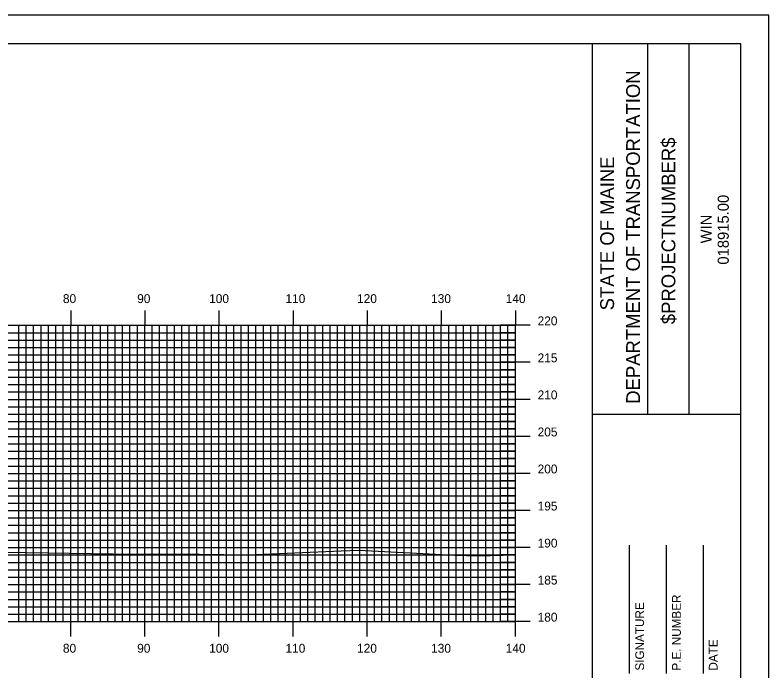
# Model space of a CAD drawing. Extents: x 1812948 to 1813291, y 442591 to 442811.
# Drawn here: x 1813186 to 1813287.7, y 442722 to 442810.5 of the extents above; entities that cross this region are included whole.
import ezdxf

# ---------------------------------------------------------------- set-up
doc = ezdxf.new("R2010")
doc.units = 0
for name, color, linetype in [('BORDER', 7, 'Continuous'), ('H_V ANNOTATION', 7, 'Continuous'), ('MAJOR', 7, 'Continuous'), ('MINOR', 7, 'Continuous'), ('PLOT BOUNDARY', 7, 'Continuous'), ('S_Roadway_Centerline', 7, 'Continuous')]:
    doc.layers.add(name, color=color, linetype=linetype)

msp = doc.modelspace()

# ---------------------------------------------------------------- linework, layer by layer
at = {"layer": 'BORDER'}
for p, q in [((1813263.86, 442596.67), (1813263.86, 442806.67)), ((1813271.31, 442756.66), (1813271.31, 442806.66)), ((1813276.9, 442756.66), (1813276.9, 442806.66)), ((1813263.86, 442756.65), (1813283.86, 442756.65)), ((1813268.86, 442721.67), (1813268.86, 442738.97)), ((1813273.86, 442721.67), (1813273.86, 442738.97)), ((1813278.86, 442721.67), (1813278.86, 442738.97))]:
    msp.add_line(p, q, dxfattribs=at)
msp.add_lwpolyline([(1812963.86, 442596.67), (1813283.86, 442596.67), (1813283.86, 442806.67), (1812963.86, 442806.67)], close=True, dxfattribs=at)
at = {"layer": 'MAJOR'}
for p, q in [((1813193.46, 442770.67), (1813193.46, 442768.67)), ((1813203.46, 442770.67), (1813203.46, 442768.67)), ((1813213.46, 442770.67), (1813213.46, 442768.67)), ((1813223.46, 442770.67), (1813223.46, 442768.67)), ((1813233.46, 442770.67), (1813233.46, 442768.67)), ((1813243.46, 442770.67), (1813243.46, 442768.67)), ((1813253.46, 442770.67), (1813253.46, 442768.67)), ((1812973.46, 442768.67), (1813253.46, 442768.67)), ((1812973.46, 442768.67), (1813253.46, 442768.67)), ((1813193.46, 442728.67), (1813193.46, 442768.67)), ((1813203.46, 442728.67), (1813203.46, 442768.67)), ((1813213.46, 442728.67), (1813213.46, 442768.67)), ((1813223.46, 442728.67), (1813223.46, 442768.67)), ((1813233.46, 442728.67), (1813233.46, 442768.67)), ((1813243.46, 442728.67), (1813243.46, 442768.67)), ((1813255.46, 442768.67), (1813251.45, 442768.67)), ((1813253.46, 442728.67), (1813253.46, 442768.67)), ((1813253.46, 442728.67), (1813253.46, 442768.67)), ((1812973.46, 442763.67), (1813253.46, 442763.67)), ((1813255.46, 442763.67), (1813251.45, 442763.67)), ((1812973.46, 442758.67), (1813253.46, 442758.67)), ((1813255.46, 442758.67), (1813251.45, 442758.67)), ((1812973.46, 442753.67), (1813253.46, 442753.67)), ((1813255.46, 442753.67), (1813251.45, 442753.67)), ((1812973.46, 442748.67), (1813253.46, 442748.67)), ((1813255.46, 442748.67), (1813251.45, 442748.67)), ((1812973.46, 442743.67), (1813253.46, 442743.67)), ((1813255.46, 442743.67), (1813251.45, 442743.67)), ((1812973.46, 442738.67), (1813253.46, 442738.67)), ((1813255.46, 442738.67), (1813251.45, 442738.67)), ((1812973.46, 442733.67), (1813253.46, 442733.67)), ((1813255.46, 442733.67), (1813251.45, 442733.67)), ((1812973.46, 442728.67), (1813253.46, 442728.67)), ((1812973.46, 442728.67), (1813253.46, 442728.67)), ((1813193.46, 442726.66), (1813193.46, 442728.67)), ((1813203.46, 442726.66), (1813203.46, 442728.67)), ((1813213.46, 442726.66), (1813213.46, 442728.67)), ((1813223.46, 442726.66), (1813223.46, 442728.67)), ((1813233.46, 442726.66), (1813233.46, 442728.67)), ((1813243.46, 442726.66), (1813243.46, 442728.67)), ((1813255.46, 442728.67), (1813251.45, 442728.67)), ((1813253.46, 442726.66), (1813253.46, 442728.67))]:
    msp.add_line(p, q, dxfattribs=at)
at = {"layer": 'MINOR'}
for p, q in [((1813186.46, 442728.67), (1813186.46, 442768.67)), ((1813187.46, 442728.67), (1813187.46, 442768.67)), ((1813188.46, 442728.67), (1813188.46, 442768.67)), ((1813189.46, 442728.67), (1813189.46, 442768.67)), ((1813190.46, 442728.67), (1813190.46, 442768.67)), ((1813191.46, 442728.67), (1813191.46, 442768.67)), ((1813192.46, 442728.67), (1813192.46, 442768.67)), ((1813194.46, 442728.67), (1813194.46, 442768.67)), ((1813195.46, 442728.67), (1813195.46, 442768.67)), ((1813196.46, 442728.67), (1813196.46, 442768.67)), ((1813197.46, 442728.67), (1813197.46, 442768.67)), ((1813198.46, 442728.67), (1813198.46, 442768.67)), ((1813199.46, 442728.67), (1813199.46, 442768.67)), ((1813200.46, 442728.67), (1813200.46, 442768.67)), ((1813201.46, 442728.67), (1813201.46, 442768.67)), ((1813202.46, 442728.67), (1813202.46, 442768.67)), ((1813204.46, 442728.67), (1813204.46, 442768.67)), ((1813205.46, 442728.67), (1813205.46, 442768.67)), ((1813206.46, 442728.67), (1813206.46, 442768.67)), ((1813207.46, 442728.67), (1813207.46, 442768.67)), ((1813208.46, 442728.67), (1813208.46, 442768.67)), ((1813209.46, 442728.67), (1813209.46, 442768.67)), ((1813210.46, 442728.67), (1813210.46, 442768.67)), ((1813211.46, 442728.67), (1813211.46, 442768.67)), ((1813212.46, 442728.67), (1813212.46, 442768.67)), ((1813214.46, 442728.67), (1813214.46, 442768.67)), ((1813215.46, 442728.67), (1813215.46, 442768.67)), ((1813216.46, 442728.67), (1813216.46, 442768.67)), ((1813217.46, 442728.67), (1813217.46, 442768.67)), ((1813218.46, 442728.67), (1813218.46, 442768.67)), ((1813219.46, 442728.67), (1813219.46, 442768.67)), ((1813220.46, 442728.67), (1813220.46, 442768.67)), ((1813221.46, 442728.67), (1813221.46, 442768.67)), ((1813222.46, 442728.67), (1813222.46, 442768.67)), ((1813224.46, 442728.67), (1813224.46, 442768.67)), ((1813225.46, 442728.67), (1813225.46, 442768.67)), ((1813226.46, 442728.67), (1813226.46, 442768.67)), ((1813227.46, 442728.67), (1813227.46, 442768.67)), ((1813228.46, 442728.67), (1813228.46, 442768.67)), ((1813229.46, 442728.67), (1813229.46, 442768.67)), ((1813230.46, 442728.67), (1813230.46, 442768.67)), ((1813231.46, 442728.67), (1813231.46, 442768.67)), ((1813232.46, 442728.67), (1813232.46, 442768.67)), ((1813234.46, 442728.67), (1813234.46, 442768.67)), ((1813235.46, 442728.67), (1813235.46, 442768.67)), ((1813236.46, 442728.67), (1813236.46, 442768.67)), ((1813237.46, 442728.67), (1813237.46, 442768.67)), ((1813238.46, 442728.67), (1813238.46, 442768.67)), ((1813239.46, 442728.67), (1813239.46, 442768.67)), ((1813240.46, 442728.67), (1813240.46, 442768.67)), ((1813241.46, 442728.67), (1813241.46, 442768.67)), ((1813242.46, 442728.67), (1813242.46, 442768.67)), ((1813244.46, 442728.67), (1813244.46, 442768.67)), ((1813245.46, 442728.67), (1813245.46, 442768.67)), ((1813246.46, 442728.67), (1813246.46, 442768.67)), ((1813247.46, 442728.67), (1813247.46, 442768.67)), ((1813248.46, 442728.67), (1813248.46, 442768.67)), ((1813249.46, 442728.67), (1813249.46, 442768.67)), ((1813250.46, 442728.67), (1813250.46, 442768.67)), ((1813251.46, 442728.67), (1813251.46, 442768.67)), ((1813252.46, 442728.67), (1813252.46, 442768.67)), ((1812973.46, 442767.67), (1813253.46, 442767.67)), ((1813253.46, 442767.67), (1813251.45, 442767.67)), ((1812973.46, 442766.67), (1813253.46, 442766.67)), ((1813253.46, 442766.67), (1813251.45, 442766.67)), ((1812973.46, 442765.67), (1813253.46, 442765.67)), ((1813253.46, 442765.67), (1813251.45, 442765.67)), ((1812973.46, 442764.67), (1813253.46, 442764.67)), ((1813253.46, 442764.67), (1813251.45, 442764.67)), ((1812973.46, 442762.67), (1813253.46, 442762.67)), ((1813253.46, 442762.67), (1813251.45, 442762.67)), ((1812973.46, 442761.67), (1813253.46, 442761.67)), ((1813253.46, 442761.67), (1813251.45, 442761.67)), ((1812973.46, 442760.67), (1813253.46, 442760.67)), ((1813253.46, 442760.67), (1813251.45, 442760.67)), ((1812973.46, 442759.67), (1813253.46, 442759.67)), ((1813253.46, 442759.67), (1813251.45, 442759.67)), ((1812973.46, 442757.67), (1813253.46, 442757.67)), ((1813253.46, 442757.67), (1813251.45, 442757.67)), ((1812973.46, 442756.67), (1813253.46, 442756.67)), ((1813253.46, 442756.67), (1813251.45, 442756.67)), ((1812973.46, 442755.67), (1813253.46, 442755.67)), ((1813253.46, 442755.67), (1813251.45, 442755.67)), ((1812973.46, 442754.67), (1813253.46, 442754.67)), ((1813253.46, 442754.67), (1813251.45, 442754.67)), ((1812973.46, 442752.67), (1813253.46, 442752.67)), ((1813253.46, 442752.67), (1813251.45, 442752.67)), ((1812973.46, 442751.67), (1813253.46, 442751.67)), ((1813253.46, 442751.67), (1813251.45, 442751.67)), ((1812973.46, 442750.67), (1813253.46, 442750.67)), ((1813253.46, 442750.67), (1813251.45, 442750.67)), ((1812973.46, 442749.67), (1813253.46, 442749.67)), ((1813253.46, 442749.67), (1813251.45, 442749.67)), ((1812973.46, 442747.67), (1813253.46, 442747.67)), ((1813253.46, 442747.67), (1813251.45, 442747.67)), ((1812973.46, 442746.67), (1813253.46, 442746.67)), ((1813253.46, 442746.67), (1813251.45, 442746.67)), ((1812973.46, 442745.67), (1813253.46, 442745.67)), ((1813253.46, 442745.67), (1813251.45, 442745.67)), ((1812973.46, 442744.67), (1813253.46, 442744.67)), ((1813253.46, 442744.67), (1813251.45, 442744.67)), ((1812973.46, 442742.67), (1813253.46, 442742.67)), ((1813253.46, 442742.67), (1813251.45, 442742.67)), ((1812973.46, 442741.67), (1813253.46, 442741.67)), ((1813253.46, 442741.67), (1813251.45, 442741.67)), ((1812973.46, 442740.67), (1813253.46, 442740.67)), ((1813253.46, 442740.67), (1813251.45, 442740.67)), ((1812973.46, 442739.67), (1813253.46, 442739.67)), ((1813253.46, 442739.67), (1813251.45, 442739.67)), ((1812973.46, 442737.67), (1813253.46, 442737.67)), ((1813253.46, 442737.67), (1813251.45, 442737.67)), ((1812973.46, 442736.67), (1813253.46, 442736.67)), ((1812973.46, 442735.67), (1813253.46, 442735.67)), ((1813253.46, 442736.67), (1813251.45, 442736.67)), ((1813253.46, 442735.67), (1813251.45, 442735.67)), ((1812973.46, 442734.67), (1813253.46, 442734.67)), ((1813253.46, 442734.67), (1813251.45, 442734.67)), ((1812973.46, 442732.67), (1813253.46, 442732.67)), ((1813253.46, 442732.67), (1813251.45, 442732.67)), ((1812973.46, 442731.67), (1813253.46, 442731.67)), ((1813253.46, 442731.67), (1813251.45, 442731.67)), ((1812973.46, 442730.67), (1813253.46, 442730.67)), ((1813253.46, 442730.67), (1813251.45, 442730.67)), ((1812973.46, 442729.67), (1813253.46, 442729.67)), ((1813253.46, 442729.67), (1813251.45, 442729.67))]:
    msp.add_line(p, q, dxfattribs=at)
at = {"layer": 'PLOT BOUNDARY'}
msp.add_lwpolyline([(1812947.67, 442590.55), (1813287.67, 442590.55), (1813287.67, 442810.55), (1812947.67, 442810.55)], close=True, dxfattribs=at)
at = {"layer": 'S_Roadway_Centerline'}
msp.add_lwpolyline([(1813083.62, 442739.65), (1813095.98, 442739.66), (1813097.88, 442739.69), (1813101.27, 442739.51), (1813114.24, 442739.35), (1813122.8, 442739.07), (1813131.09, 442738.73), (1813144.26, 442738.29), (1813147.01, 442738.13), (1813156.22, 442738.12), (1813163.12, 442738.13), (1813164.63, 442738.16), (1813176.93, 442738.26), (1813180.7, 442738.09), (1813187.39, 442738.01), (1813199.2, 442737.83), (1813210.85, 442737.78), (1813217.43, 442737.68), (1813229.94, 442738.24), (1813232.32, 442738.32), (1813245.29, 442737.66), (1813248.44, 442737.56), (1813253.46, 442737.68)], dxfattribs=at)

# ---------------------------------------------------------------- texts
at = {"layer": 'BORDER'}
for s, height, p in [('DEPARTMENT OF TRANSPORTATION', 1.8635, (1813270.27, 442758.08)), ('$PROJECTNUMBER$', 1.8635, (1813275.04, 442768.82)), ('STATE OF MAINE', 1.8635, (1813266.77, 442770.69)), ('018915.00', 1.491, (1813282.25, 442776.86)), ('WIN', 1.491, (1813279.93, 442779.73)), ('P.E. NUMBER', 1.1811, (1813275.78, 442722.06)), ('SIGNATURE', 1.181, (1813270.82, 442722.06)), ('DATE', 1.181, (1813280.74, 442722.06))]:
    msp.add_text(s, height=height, rotation=90, dxfattribs=at).set_placement(p)
at = {"layer": 'H_V ANNOTATION'}
for s, p in [('80', (1813192.41, 442771.67)), ('90', (1813202.43, 442771.67)), ('100', (1813212.14, 442771.67)), ('110', (1813222.44, 442771.67)), ('120', (1813232.1, 442771.67)), ('130', (1813242.09, 442771.67)), ('140', (1813252.16, 442771.67)), ('220', (1813256.46, 442768.67)), ('215', (1813256.46, 442763.67)), ('210', (1813256.46, 442758.67)), ('205', (1813256.46, 442753.67)), ('200', (1813256.46, 442748.67)), ('195', (1813256.46, 442743.67)), ('190', (1813256.46, 442738.67)), ('185', (1813256.46, 442733.67)), ('180', (1813256.46, 442728.67)), ('80', (1813192.41, 442724.47)), ('90', (1813202.43, 442724.47)), ('100', (1813212.14, 442724.47)), ('110', (1813222.44, 442724.47)), ('120', (1813232.1, 442724.47)), ('130', (1813242.09, 442724.47)), ('140', (1813252.16, 442724.47))]:
    msp.add_text(s, height=1.2, dxfattribs=at).set_placement(p)

doc.saveas('drawing.dxf')
